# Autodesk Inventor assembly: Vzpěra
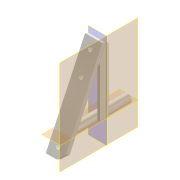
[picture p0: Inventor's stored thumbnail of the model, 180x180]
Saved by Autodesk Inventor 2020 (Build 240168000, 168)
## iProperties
Created: 2025-03
Part Number: Vzpěra
Document SubType Name: Assembly
Designer: doma
Mass: 1106.48 g
Surface Area: 401.387 cm^2
Volume: 140.952 cm^3
Density: 7.85 g/cm^3
Author: doma
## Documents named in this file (4)
- C:\Users\doma\Desktop\Pásovka záloha\Workgroups\NotInProject\Svařenec vzpěra.iam
- C:\Users\doma\Desktop\Pásovka záloha\Workgroups\NotInProject\Vzpěra pásovina.ipt
- C:\Users\doma\Desktop\Pásovka záloha\Workgroups\NotInProject\Vzpěra tyč.ipt
- C:\Users\doma\Desktop\Pásovka záloha\Workgroups\NotInProject\Vzpěra výztuha.ipt
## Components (3 placed, 3 different names)
1. Vzpěra pásovina:1 — Proti sobě:4, Stejný směr:1, Stejný směr:2, Stejný směr:3, Stejný směr:4
2. Vzpěra tyč:1 — Tečnost:1, Proti sobě:5, Stejný směr:3, Proti sobě:6
3. Vzpěra výztuha:1 — Tečnost:1, Proti sobě:4, Proti sobě:5, Stejný směr:1, Stejný směr:2
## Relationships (8: Flush 4, Mate 3, Tangent 1)
- Tečnost:1 [Tangent]: Vzpěra tyč:1 ↔ Vzpěra výztuha:1
- Proti sobě:4 [Mate]: Vzpěra pásovina:1 ↔ Vzpěra výztuha:1
- Proti sobě:5 [Mate]: Vzpěra tyč:1 ↔ Vzpěra výztuha:1
- Stejný směr:1 [Flush]: Vzpěra pásovina:1 ↔ Vzpěra výztuha:1
- Stejný směr:2 [Flush]: Vzpěra pásovina:1 ↔ Vzpěra výztuha:1
- Stejný směr:3 [Flush]: Vzpěra pásovina:1 ↔ Vzpěra tyč:1
- Stejný směr:4 [Flush]: Vzpěra pásovina:1
- Proti sobě:6 [Mate]: Vzpěra tyč:1
